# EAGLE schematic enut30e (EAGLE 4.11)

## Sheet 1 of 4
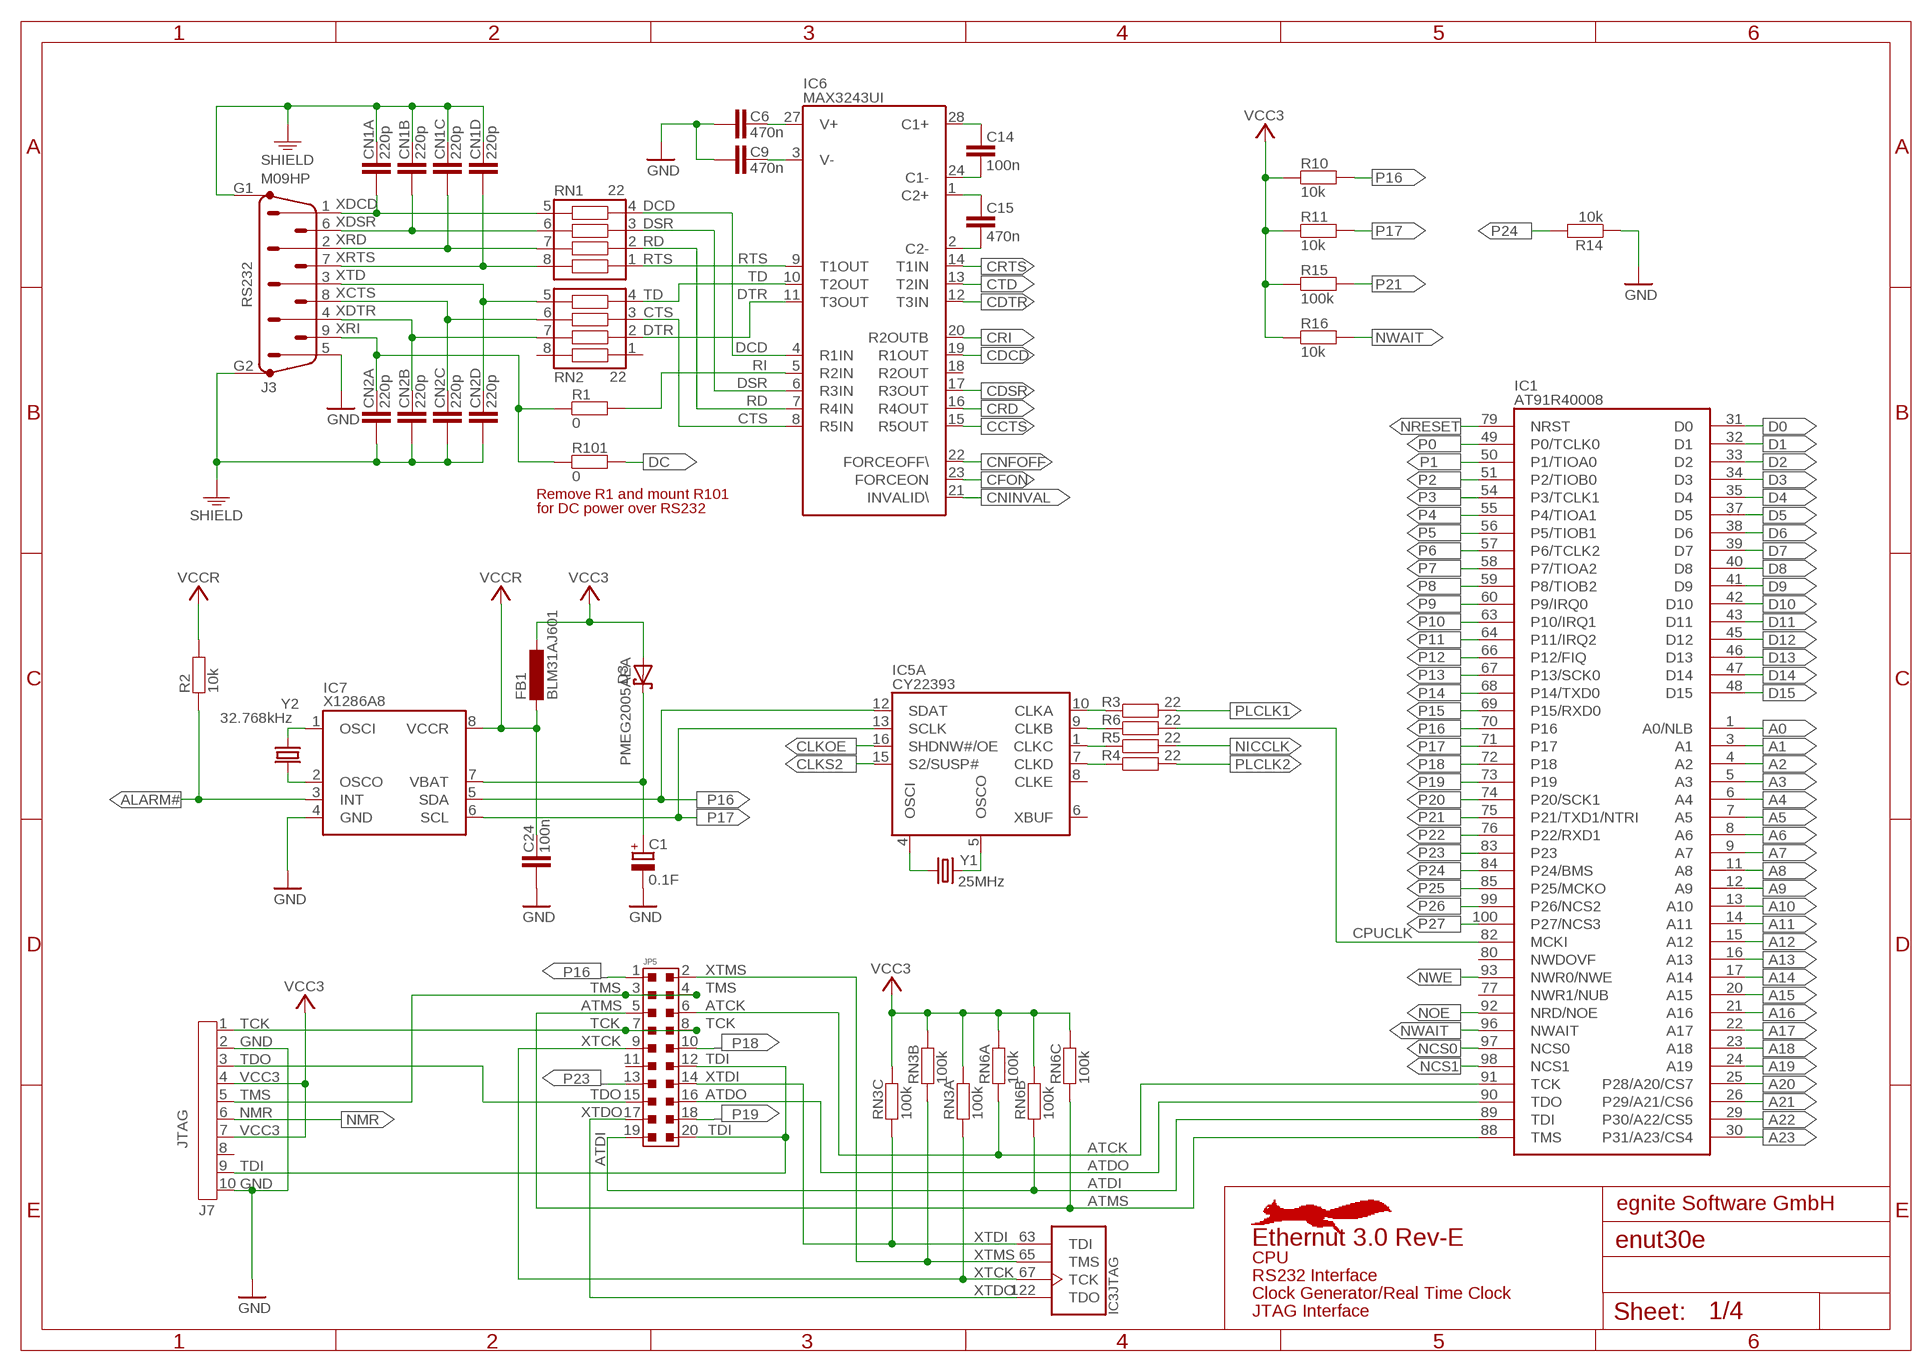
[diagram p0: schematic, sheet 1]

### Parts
C1  0.1F  FG0H104Z135  [CDL13_5]
C6  470n  C0603  [C0603]
C9  470n  C0603  [C0603]
C14  100n  C0603  [C0603]
C15  470n  C0603  [C0603]
C24  100n  C0603  [C0603]
CN1  220p  NCA1206  [NCA1206]
CN2  220p  NCA1206  [NCA1206]
D3  PMEG2005AEA  [SOD323]
FB1  BLM31AJ601  BLM31A  [BLM31]
IC1  AT91R40008  [TQFP100]
IC3  XC95144XLTQ144  [XC95_TQ144]
IC5  CY22393  [TSSOP16]
IC6  MAX3243UI  [TSSOP28]
IC7  X1286A8  [SOIC-8-209]
J3  M09HP  [M09HP]
J7  ML10A  [ML10A]
JP5  JP10X2  [JP10X2]
R1  0  R0603  [R0603]
R2  10k  R0603  [R0603]
R3  22  R0603  [R0603]
R4  22  R0603  [R0603]
R5  22  R0603  [R0603]
R6  22  R0603  [R0603]
R10  10k  R0603  [R0603]
R11  10k  R0603  [R0603]
R14  10k  R0603  [R0603]
R15  100k  R0603  [R0603]
R16  10k  R0603  [R0603]
R101  0  R1206  [R1206]
RN1  22  CAY16N  [CAY16]
RN2  22  CAY16N  [CAY16]
RN3  100k  CAY16  [CAY16]
RN6  100k  CAY16  [CAY16]
Y1  25MHz  CRYSTALHC49SM  [HC49SM]
Y2  32.768kHz  MC-146  [MC-146]

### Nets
A0: IC1.1(A0/NLB) ; also sheet 2
A1: IC1.3(A1) ; also sheet 2
A2: IC1.4(A2) ; also sheet 2,3
A3: IC1.5(A3) ; also sheet 2
A4: IC1.6(A4) ; also sheet 2
A5: IC1.7(A5) ; also sheet 2
A6: IC1.8(A6) ; also sheet 2
A7: IC1.9(A7) ; also sheet 2
A8 [AddrbusH]: IC1.11(A8) ; also sheet 2
A9 [AddrbusH]: IC1.12(A9) ; also sheet 2
A10 [AddrbusH]: IC1.13(A10) ; also sheet 2
A11 [AddrbusH]: IC1.14(A11) ; also sheet 2
A12 [AddrbusH]: IC1.15(A12) ; also sheet 2
A13 [AddrbusH]: IC1.16(A13) ; also sheet 2
A14 [AddrbusH]: IC1.17(A14) ; also sheet 2
A15 [AddrbusH]: IC1.20(A15) ; also sheet 2
A16: IC1.21(A16) ; also sheet 2
A17: IC1.22(A17) ; also sheet 2
A18: IC1.23(A18) ; also sheet 2
A19: IC1.24(A19) ; also sheet 2
A20: IC1.25(P28/A20/CS7) ; also sheet 2
A21: IC1.26(P29/A21/CS6) ; also sheet 2
A22: IC1.29(P30/A22/CS5) ; also sheet 2
A23: IC1.30(P31/A23/CS4) ; also sheet 2
ALARM#: IC7.3(INT) R2.1 ; also sheet 2
ATCK: IC1.91(TCK) JP5.6 RN6.1
ATDI: IC1.89(TDI) JP5.19 RN6.2
ATDO: IC1.90(TDO) JP5.16
ATMS: IC1.88(TMS) JP5.5 RN6.3
CCTS: IC6.15(R5OUT) ; also sheet 2
CDCD: IC6.19(R1OUT) ; also sheet 2
CDSR: IC6.17(R3OUT) ; also sheet 2
CDTR: IC6.12(T3IN) ; also sheet 2
CFON: IC6.23(FORCEON) ; also sheet 2
CLKA: IC5.10(A:CLKA) R3.1
CLKB: IC5.9(A:CLKB) R6.1
CLKC: IC5.1(A:CLKC) R5.1
CLKD: IC5.7(A:CLKD) R4.1
CLKOE: IC5.16(A:SHDNW#/OE) ; also sheet 2
CLKS2: IC5.15(A:S2/SUSP#) ; also sheet 2
CNFOFF: IC6.22(FORCEOFF\) ; also sheet 2
CNINVAL: IC6.21(INVALID\) ; also sheet 2
CPUCLK: IC1.82(MCKI) R6.2
CRD: IC6.16(R4OUT) ; also sheet 2
CRI: IC6.20(R2OUTB) ; also sheet 2
CRTS: IC6.14(T1IN) ; also sheet 2
CTD: IC6.13(T2IN) ; also sheet 2
CTS: IC6.8(R5IN) RN2.3
D0 [Databus]: IC1.31(D0) ; also sheet 2,3
D1 [Databus]: IC1.32(D1) ; also sheet 2,3
D2 [Databus]: IC1.33(D2) ; also sheet 2,3
D3 [Databus]: IC1.34(D3) ; also sheet 2,3
D4 [Databus]: IC1.35(D4) ; also sheet 2,3
D5 [Databus]: IC1.37(D5) ; also sheet 2,3
D6 [Databus]: IC1.38(D6) ; also sheet 2,3
D7 [Databus]: IC1.39(D7) ; also sheet 2,3
D8: IC1.40(D8) ; also sheet 2,3
D9: IC1.41(D9) ; also sheet 2,3
D10: IC1.42(D10) ; also sheet 2,3
D11: IC1.43(D11) ; also sheet 2,3
D12: IC1.45(D12) ; also sheet 2,3
D13: IC1.46(D13) ; also sheet 2,3
D14: IC1.47(D14) ; also sheet 2,3
D15: IC1.48(D15) ; also sheet 2,3
DC: R101.2 ; also sheet 2,4
DCD: IC6.4(R1IN) RN1.4
DSR: IC6.6(R3IN) RN1.3
DTR: IC6.11(T3OUT) RN2.2
GND: C1.- C6.2 C9.2 C24.2 IC7.4(GND) J3.5 J7.2 J7.10 R14.1 ; also sheet 2,3,4
N$1: C6.1 IC6.27(V+)
N$2: C9.1 IC6.3(V-)
N$3: C15.2 IC6.2(C2-)
N$8: C15.1 IC6.1(C2+)
N$9: C14.2 IC6.24(C1-)
N$10: C14.1 IC6.28(C1+)
N$45: IC5.4(A:OSCI) Y1.2
N$46: IC5.5(A:OSCO) Y1.1
NCS0: IC1.97(NCS0) ; also sheet 2
NCS1: IC1.98(NCS1) ; also sheet 3
NICCLK: R5.2 ; also sheet 3
NMR: J7.6 ; also sheet 2,4
NOE: IC1.92(NRD/NOE) ; also sheet 2,3
NRESET: IC1.79(NRST) ; also sheet 2,3,4
NWAIT: IC1.96(NWAIT) R16.2 ; also sheet 2,3
NWE: IC1.93(NWR0/NWE) ; also sheet 2,3
P0: IC1.49(P0/TCLK0) ; also sheet 2
P1: IC1.50(P1/TIOA0) ; also sheet 2
P2: IC1.51(P2/TIOB0) ; also sheet 2
P3: IC1.54(P3/TCLK1) ; also sheet 2
P4: IC1.55(P4/TIOA1) ; also sheet 2
P5: IC1.56(P5/TIOB1) ; also sheet 2
P6: IC1.57(P6/TCLK2) ; also sheet 2
P7: IC1.58(P7/TIOA2) ; also sheet 2
P8: IC1.59(P8/TIOB2) ; also sheet 2
P9: IC1.60(P9/IRQ0) ; also sheet 2
P10: IC1.63(P10/IRQ1) ; also sheet 3
P11: IC1.64(P11/IRQ2) ; also sheet 2
P12: IC1.66(P12/FIQ) ; also sheet 2
P13: IC1.67(P13/SCK0) ; also sheet 2
P14: IC1.68(P14/TXD0) ; also sheet 2
P15: IC1.69(P15/RXD0) ; also sheet 2
P16: IC1.70(P16) IC5.12(A:SDAT) IC7.5(SDA) JP5.1 R10.2 ; also sheet 2
P17: IC1.71(P17) IC5.13(A:SCLK) IC7.6(SCL) R11.2 ; also sheet 2
P18: IC1.72(P18) JP5.10 ; also sheet 2
P19: IC1.73(P19) JP5.18 ; also sheet 2
P20: IC1.74(P20/SCK1) ; also sheet 2
P21: IC1.75(P21/TXD1/NTRI) R15.2 ; also sheet 2
P22: IC1.76(P22/RXD1) ; also sheet 2
P23: IC1.83(P23) JP5.13 ; also sheet 2
P24: IC1.84(P24/BMS) R14.2 ; also sheet 2,3
P25: IC1.85(P25/MCKO) ; also sheet 2
P26: IC1.99(P26/NCS2) ; also sheet 2
P27: IC1.100(P27/NCS3) ; also sheet 2
PLCLK1: R3.2 ; also sheet 2
PLCLK2: R4.2 ; also sheet 2
RD: IC6.7(R4IN) RN1.2
RI: IC6.5(R2IN) R1.2
RTCX1: IC7.1(OSCI) Y2.1
RTCX2: IC7.2(OSCO) Y2.4
RTS: IC6.9(T1OUT) RN1.1
SHIELD: CN1.1 CN1.2 CN1.3 CN1.4 CN2.5 CN2.6 CN2.7 CN2.8 J3.G1 J3.G2 ; also sheet 2,3
TCK: J7.1 JP5.7 JP5.8
TD: IC6.10(T2OUT) RN2.4
TDI: J7.9 JP5.12 JP5.20
TDO: J7.3 JP5.15
TMS: J7.5 JP5.3 JP5.4
VBAT: C1.+ D3.C IC7.7(VBAT)
VCC3: D3.A FB1.1 J7.4 J7.7 R10.1 R11.1 R15.1 R16.1 RN3.6 RN3.7 RN3.8 RN6.6 RN6.7 RN6.8 ; also sheet 2,4
VCCR: C24.1 FB1.2 IC7.8(VCCR) R2.2
XCTS: CN2.3 J3.8 RN2.6
XDCD: CN1.8 J3.1 RN1.5
XDSR: CN1.7 J3.6 RN1.6
XDTR: CN2.2 J3.4 RN2.7
XRD: CN1.6 J3.2 RN1.7
XRI: CN2.1 J3.9 R1.1 R101.1
XRTS: CN1.5 J3.7 RN1.8
XTCK: IC3.67(TCK) JP5.9 RN3.1
XTD: CN2.4 J3.3 RN2.5
XTDI: IC3.63(TDI) JP5.14 RN3.3
XTDO: IC3.122(TDO) JP5.17
XTMS: IC3.65(TMS) JP5.2 RN3.2
Unconnected: J7.8 JP5.11 RN2.1 RN2.8 RN3.4 RN3.5 RN6.4 RN6.5

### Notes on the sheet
- RS232
- Remove R1 and mount R101
- for DC power over RS232
- JTAG
- egnite Software GmbH
- Ethernut 3.0 Rev-E
- CPU
- RS232 Interface
- Clock Generator/Real Time Clock
- JTAG Interface

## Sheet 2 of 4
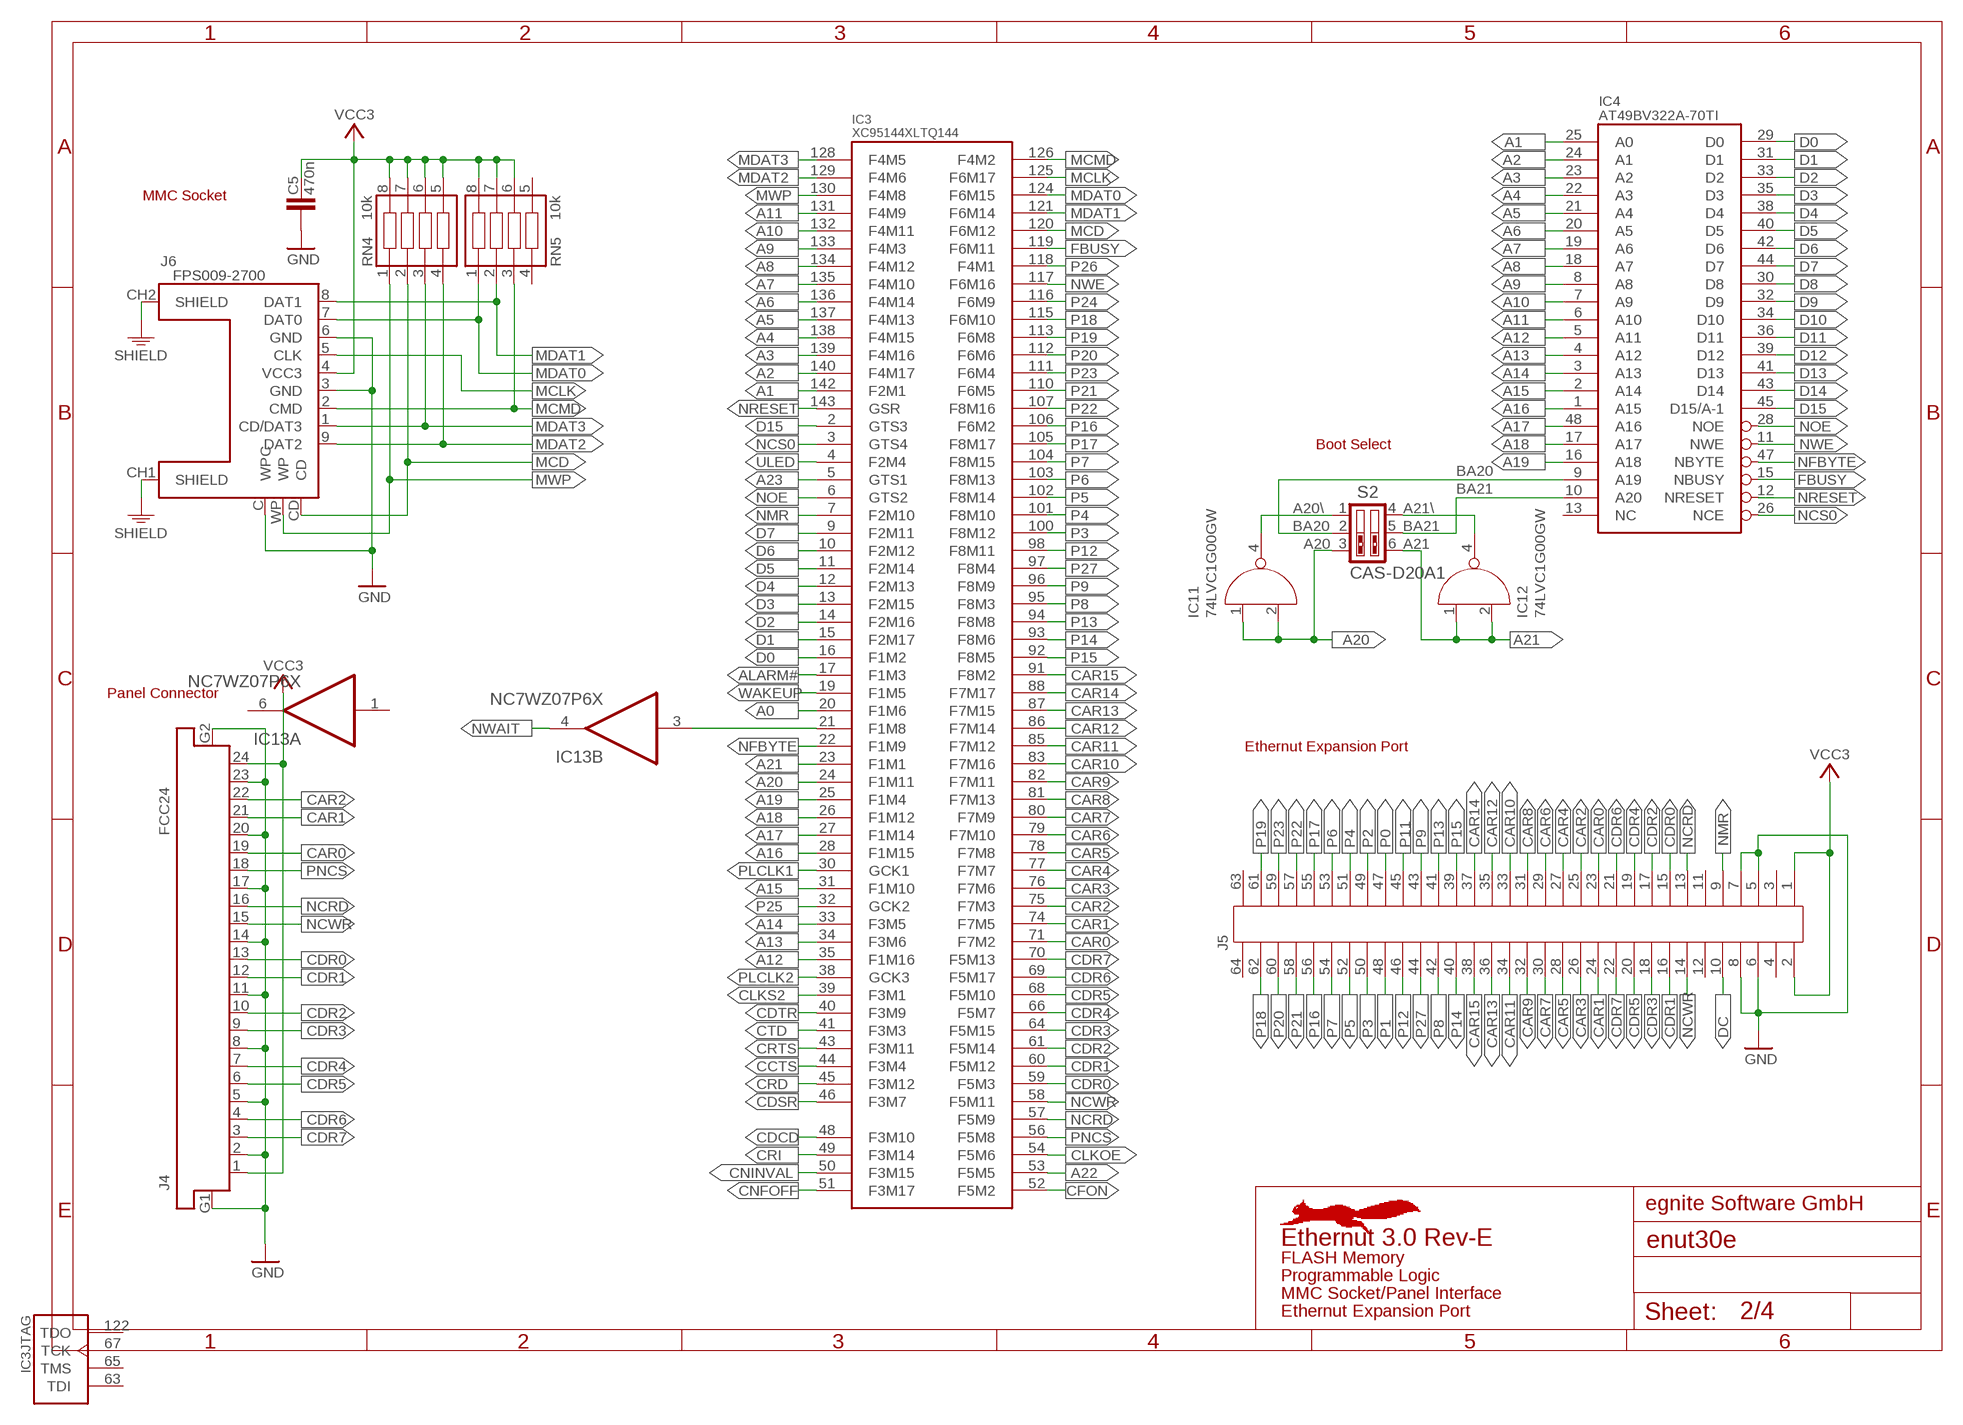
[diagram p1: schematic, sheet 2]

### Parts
C5  470n  C0603  [C0603]
IC4  AT49BV322A-70TI  [TSOP48]
IC11  74LVC1G00GW  [SOT353]
IC12  74LVC1G00GW  [SOT353]
IC13  NC7WZ07P6X  [SOT363]
J4  FCC24  [FFC-52437]
J5  NUTEXP  [NUTEXP]
J6  FPS009-2700  [FPS009-2700]
RN4  10k  CAY16N  [CAY16]
RN5  10k  CAY16N  [CAY16]
S2  CAS-D20A1  [CAS-D20A1]

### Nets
A0: IC3.20(F1M6) ; also sheet 1
A1: IC3.142(F2M1) IC4.25(A0) ; also sheet 1
A2: IC3.140(F4M17) IC4.24(A1) ; also sheet 1,3
A3: IC3.139(F4M16) IC4.23(A2) ; also sheet 1
A4: IC3.138(F4M15) IC4.22(A3) ; also sheet 1
A5: IC3.137(F4M13) IC4.21(A4) ; also sheet 1
A6: IC3.136(F4M14) IC4.20(A5) ; also sheet 1
A7: IC3.135(F4M10) IC4.19(A6) ; also sheet 1
A8 [AddrbusH]: IC3.134(F4M12) IC4.18(A7) ; also sheet 1
A9 [AddrbusH]: IC3.133(F4M3) IC4.8(A8) ; also sheet 1
A10 [AddrbusH]: IC3.132(F4M11) IC4.7(A9) ; also sheet 1
A11 [AddrbusH]: IC3.131(F4M9) IC4.6(A10) ; also sheet 1
A12 [AddrbusH]: IC3.35(F1M16) IC4.5(A11) ; also sheet 1
A13 [AddrbusH]: IC3.34(F3M6) IC4.4(A12) ; also sheet 1
A14 [AddrbusH]: IC3.33(F3M5) IC4.3(A13) ; also sheet 1
A15 [AddrbusH]: IC3.31(F1M10) IC4.2(A14) ; also sheet 1
A16: IC3.28(F1M15) IC4.1(A15) ; also sheet 1
A17: IC3.27(F1M14) IC4.48(A16) ; also sheet 1
A18: IC3.26(F1M12) IC4.17(A17) ; also sheet 1
A19: IC3.25(F1M4) IC4.16(A18) ; also sheet 1
A20: IC3.24(F1M11) IC11.1(I0) IC11.2(I1) S2.3(3A) ; also sheet 1
A20\: IC11.4(O) S2.1(1A)
A21: IC3.23(F1M1) IC12.1(I0) IC12.2(I1) S2.6(3B) ; also sheet 1
A21\: IC12.4(O) S2.4(1B)
A22: IC3.53(F5M5) ; also sheet 1
A23: IC3.5(GTS1) ; also sheet 1
ALARM#: IC3.17(F1M3) ; also sheet 1
BA20: IC4.9(A19) S2.2(2A)
BA21: IC4.10(A20) S2.5(2B)
CAR0: IC3.71(F7M2) J4.19 J5.23
CAR1: IC3.74(F7M5) J4.21 J5.24
CAR2: IC3.75(F7M3) J4.22 J5.25
CAR3: IC3.76(F7M6) J5.26
CAR4: IC3.77(F7M7) J5.27
CAR5: IC3.78(F7M8) J5.28
CAR6: IC3.79(F7M10) J5.29
CAR7: IC3.80(F7M9) J5.30
CAR8: IC3.81(F7M13) J5.31
CAR9: IC3.82(F7M11) J5.32
CAR10: IC3.83(F7M16) J5.33
CAR11: IC3.85(F7M12) J5.34
CAR12: IC3.86(F7M14) J5.35
CAR13: IC3.87(F7M15) J5.36
CAR14: IC3.88(F7M17) J5.37
CAR15: IC3.91(F8M2) J5.38
CCTS: IC3.44(F3M4) ; also sheet 1
CDCD: IC3.48(F3M10) ; also sheet 1
CDR0: IC3.59(F5M3) J4.13 J5.15
CDR1: IC3.60(F5M12) J4.12 J5.16
CDR2: IC3.61(F5M14) J4.10 J5.17
CDR3: IC3.64(F5M15) J4.9 J5.18
CDR4: IC3.66(F5M7) J4.7 J5.19
CDR5: IC3.68(F5M10) J4.6 J5.20
CDR6: IC3.69(F5M17) J4.4 J5.21
CDR7: IC3.70(F5M13) J4.3 J5.22
CDSR: IC3.46(F3M7) ; also sheet 1
CDTR: IC3.40(F3M9) ; also sheet 1
CFON: IC3.52(F5M2) ; also sheet 1
CLKOE: IC3.54(F5M6) ; also sheet 1
CLKS2: IC3.39(F3M1) ; also sheet 1
CNFOFF: IC3.51(F3M17) ; also sheet 1
CNINVAL: IC3.50(F3M15) ; also sheet 1
CRD: IC3.45(F3M12) ; also sheet 1
CRI: IC3.49(F3M14) ; also sheet 1
CRTS: IC3.43(F3M11) ; also sheet 1
CTD: IC3.41(F3M3) ; also sheet 1
D0 [Databus]: IC3.16(F1M2) IC4.29(D0) ; also sheet 1,3
D1 [Databus]: IC3.15(F2M17) IC4.31(D1) ; also sheet 1,3
D2 [Databus]: IC3.14(F2M16) IC4.33(D2) ; also sheet 1,3
D3 [Databus]: IC3.13(F2M15) IC4.35(D3) ; also sheet 1,3
D4 [Databus]: IC3.12(F2M13) IC4.38(D4) ; also sheet 1,3
D5 [Databus]: IC3.11(F2M14) IC4.40(D5) ; also sheet 1,3
D6 [Databus]: IC3.10(F2M12) IC4.42(D6) ; also sheet 1,3
D7 [Databus]: IC3.9(F2M11) IC4.44(D7) ; also sheet 1,3
D8: IC4.30(D8) ; also sheet 1,3
D9: IC4.32(D9) ; also sheet 1,3
D10: IC4.34(D10) ; also sheet 1,3
D11: IC4.36(D11) ; also sheet 1,3
D12: IC4.39(D12) ; also sheet 1,3
D13: IC4.41(D13) ; also sheet 1,3
D14: IC4.43(D14) ; also sheet 1,3
D15: IC3.2(GTS3) IC4.45(D15/A-1) ; also sheet 1,3
DC: J5.10 ; also sheet 1,4
FBUSY: IC3.119(F6M11) IC4.15(NBUSY)
GND: C5.2 J4.2 J4.5 J4.8 J4.11 J4.14 J4.17 J4.20 J4.23 J4.G1 J4.G2 J5.5 J5.6 J5.7 J5.8 J6.3(GND) J6.6(GND) J6.C(WPC) ; also sheet 1,3,4
MCD: IC3.120(F6M12) J6.CD RN4.2
MCLK: IC3.125(F6M17) J6.5(CLK)
MCMD: IC3.126(F4M2) J6.2(CMD) RN5.3
MDAT0: IC3.124(F6M15) J6.7(DAT0) RN5.1
MDAT1: IC3.121(F6M14) J6.8(DAT1) RN5.2
MDAT2: IC3.129(F4M6) J6.9(DAT2) RN4.4
MDAT3: IC3.128(F4M5) J6.1(CD/DAT3) RN4.3
MWP: IC3.130(F4M8) J6.WP RN4.1
NCRD: IC3.57(F5M9) J4.16 J5.13
NCS0: IC3.3(GTS4) IC4.26(NCE) ; also sheet 1
NCWAIT: IC3.21(F1M8) IC13.3(B:I)
NCWR: IC3.58(F5M11) J4.15 J5.14
NFBYTE: IC3.22(F1M9) IC4.47(NBYTE)
NMR: IC3.7(F2M10) J5.9 ; also sheet 1,4
NOE: IC3.6(GTS2) IC4.28(NOE) ; also sheet 1,3
NRESET: IC3.143(GSR) IC4.12(NRESET) ; also sheet 1,3,4
NWAIT: IC13.4(B:O) ; also sheet 1,3
NWE: IC3.117(F6M16) IC4.11(NWE) ; also sheet 1,3
P0: J5.47 ; also sheet 1
P1: J5.48 ; also sheet 1
P2: J5.49 ; also sheet 1
P3: IC3.100(F8M12) J5.50 ; also sheet 1
P4: IC3.101(F8M10) J5.51 ; also sheet 1
P5: IC3.102(F8M14) J5.52 ; also sheet 1
P6: IC3.103(F8M13) J5.53 ; also sheet 1
P7: IC3.104(F8M15) J5.54 ; also sheet 1
P8: IC3.95(F8M3) J5.42 ; also sheet 1
P9: IC3.96(F8M9) J5.43 ; also sheet 1
P11: J5.45 ; also sheet 1
P12: IC3.98(F8M11) J5.46 ; also sheet 1
P13: IC3.94(F8M8) J5.41 ; also sheet 1
P14: IC3.93(F8M6) J5.40 ; also sheet 1
P15: IC3.92(F8M5) J5.39 ; also sheet 1
P16: IC3.106(F6M2) J5.56 ; also sheet 1
P17: IC3.105(F8M17) J5.55 ; also sheet 1
P18: IC3.115(F6M10) J5.62 ; also sheet 1
P19: IC3.113(F6M8) J5.61 ; also sheet 1
P20: IC3.112(F6M6) J5.60 ; also sheet 1
P21: IC3.110(F6M5) J5.58 ; also sheet 1
P22: IC3.107(F8M16) J5.57 ; also sheet 1
P23: IC3.111(F6M4) J5.59 ; also sheet 1
P24: IC3.116(F6M9) ; also sheet 1,3
P25: IC3.32(GCK2) ; also sheet 1
P26: IC3.118(F4M1) ; also sheet 1
P27: IC3.97(F8M4) J5.44 ; also sheet 1
PLCLK1: IC3.30(GCK1) ; also sheet 1
PLCLK2: IC3.38(GCK3) ; also sheet 1
PNCS: IC3.56(F5M8) J4.18
SHIELD: J6.CH1(SHIELD) J6.CH2(SHIELD) ; also sheet 1,3
ULED: IC3.4(F2M4) ; also sheet 4
VCC3: C5.1 J4.1 J4.24 J5.1 J5.2 J6.4(VCC3) RN4.5 RN4.6 RN4.7 RN4.8 RN5.6 RN5.7 RN5.8 ; also sheet 1,4
WAKEUP: IC3.19(F1M5) ; also sheet 3
Unconnected: IC4.13(NC) J5.3 J5.4 J5.11 J5.12 J5.63 J5.64 RN5.4 RN5.5

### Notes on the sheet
- MMC Socket
- Boot Select
- Panel Connector
- Ethernut Expansion Port
- egnite Software GmbH
- Ethernut 3.0 Rev-E
- FLASH Memory
- Programmable Logic
- MMC Socket/Panel Interface
- Ethernut Expansion Port

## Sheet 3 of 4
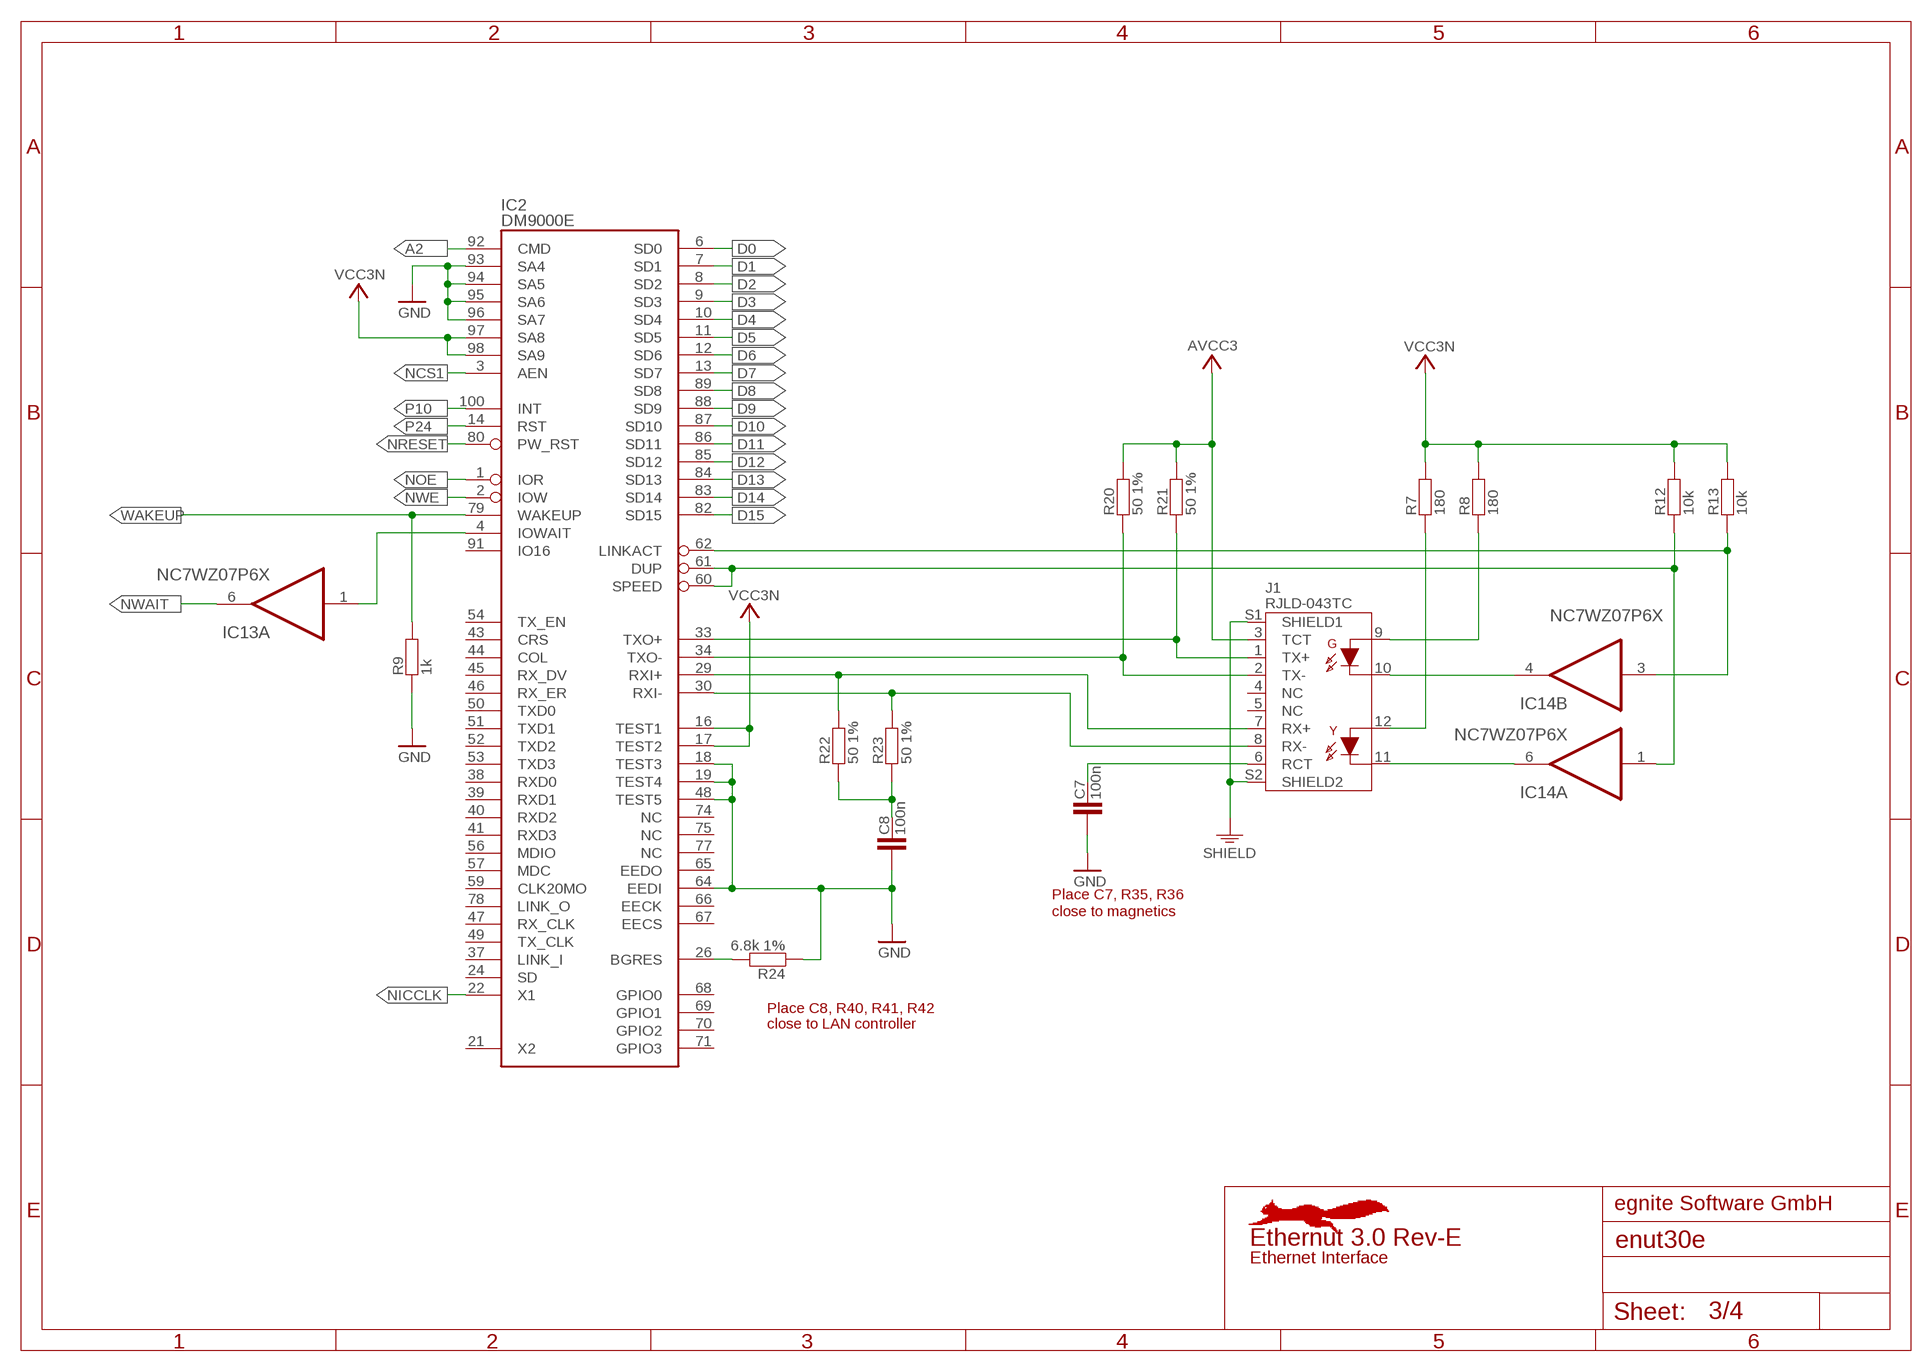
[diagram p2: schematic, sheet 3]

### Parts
C7  100n  C0603  [C0603]
C8  100n  C0603  [C0603]
IC2  DM9000E  [LQFP100]
IC14  NC7WZ07P6X  [SOT363]
J1  RJLD-043TC  [RJLD-043TC]
R7  180  R0603  [R0603]
R8  180  R0603  [R0603]
R9  1k  R0603  [R0603]
R12  10k  R0603  [R0603]
R13  10k  R0603  [R0603]
R20  50 1%  R0603  [R0603]
R21  50 1%  R0603  [R0603]
R22  50 1%  R0603  [R0603]
R23  50 1%  R0603  [R0603]
R24  6.8k 1%  R0603  [R0603]

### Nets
A2: IC2.92(CMD) ; also sheet 1,2
ALEDA: J1.12(YA) R7.1
ALEDC: IC14.6(A:O) J1.11(YC)
AVCC3: J1.3(TCT) R20.2 R21.2 ; also sheet 4
BIAS: IC2.26(BGRES) R24.2
D0 [Databus]: IC2.6(SD0) ; also sheet 1,2
D1 [Databus]: IC2.7(SD1) ; also sheet 1,2
D2 [Databus]: IC2.8(SD2) ; also sheet 1,2
D3 [Databus]: IC2.9(SD3) ; also sheet 1,2
D4 [Databus]: IC2.10(SD4) ; also sheet 1,2
D5 [Databus]: IC2.11(SD5) ; also sheet 1,2
D6 [Databus]: IC2.12(SD6) ; also sheet 1,2
D7 [Databus]: IC2.13(SD7) ; also sheet 1,2
D8: IC2.89(SD8) ; also sheet 1,2
D9: IC2.88(SD9) ; also sheet 1,2
D10: IC2.87(SD10) ; also sheet 1,2
D11: IC2.86(SD11) ; also sheet 1,2
D12: IC2.85(SD12) ; also sheet 1,2
D13: IC2.84(SD13) ; also sheet 1,2
D14: IC2.83(SD14) ; also sheet 1,2
D15: IC2.82(SD15) ; also sheet 1,2
ETHWAIT: IC2.4(IOWAIT) IC13.1(A:I)
GND: C7.2 C8.2 IC2.18(TEST3) IC2.19(TEST4) IC2.48(TEST5) IC2.64(EEDI) IC2.93(SA4) IC2.94(SA5) IC2.95(SA6) IC2.96(SA7) R9.1 R24.1 ; also sheet 1,2,4
LLEDA: J1.9(GA) R8.1
LLEDC: IC14.4(B:O) J1.10(GC)
NCS1: IC2.3(AEN) ; also sheet 1
NICCLK: IC2.22(X1) ; also sheet 1
NLEDA\: IC2.62(LINKACT) IC14.3(B:I) R13.1
NLEDB\: IC2.60(SPEED) IC2.61(DUP) IC14.1(A:I) R12.1
NOE: IC2.1(IOR) ; also sheet 1,2
NRESET: IC2.80(PW_RST) ; also sheet 1,2,4
NWAIT: IC13.6(A:O) ; also sheet 1,2
NWE: IC2.2(IOW) ; also sheet 1,2
P10: IC2.100(INT) ; also sheet 1
P24: IC2.14(RST) ; also sheet 1,2
RCT: C7.1 J1.6(RCT)
RXIC: C8.1 R22.1 R23.1
SHIELD: J1.S1(SHIELD1) J1.S2(SHIELD2) ; also sheet 1,2
TPI+: IC2.29(RXI+) J1.7(RX+) R22.2
TPI-: IC2.30(RXI-) J1.8(RX-) R23.2
TPO+: IC2.33(TXO+) J1.1(TX+) R21.1
TPO-: IC2.34(TXO-) J1.2(TX-) R20.1
VCC3N: IC2.16(TEST1) IC2.17(TEST2) IC2.97(SA8) IC2.98(SA9) R7.2 R8.2 R12.2 R13.2 ; also sheet 4
WAKEUP: IC2.79(WAKEUP) R9.2 ; also sheet 2
Unconnected: J1.4(NC) J1.5(NC)

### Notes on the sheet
- Place C7, R35, R36
- close to magnetics
- Place C8, R40, R41, R42
- close to LAN controller
- egnite Software GmbH
- Ethernut 3.0 Rev-E
- Ethernet Interface

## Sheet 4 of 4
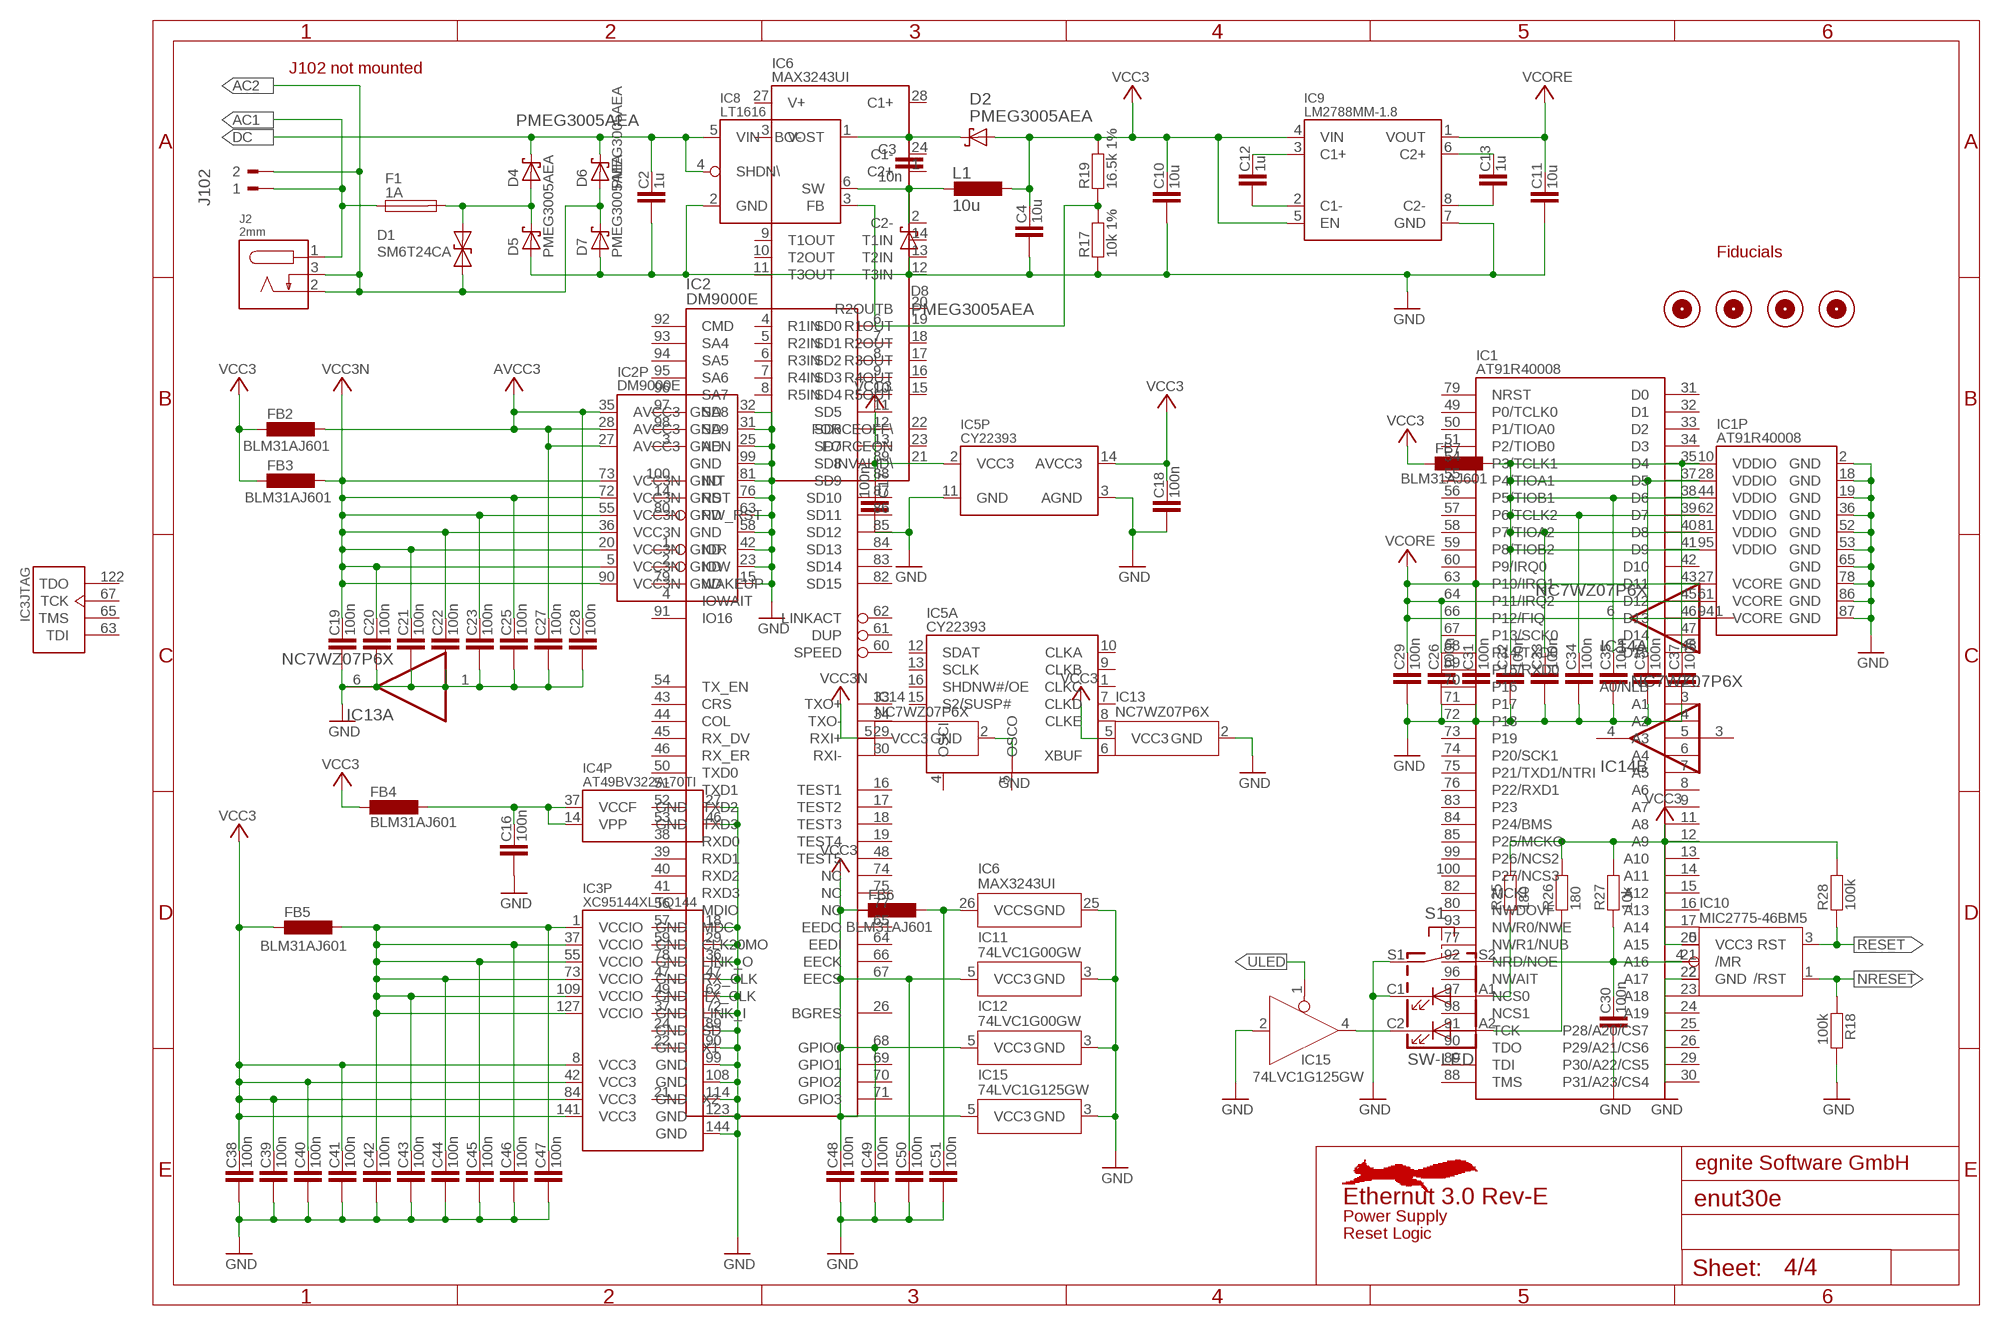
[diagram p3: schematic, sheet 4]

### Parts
C2  1u  C0805  [C0805]
C3  10n  C0603  [C0603]
C4  10u  C0805  [C0805]
C10  10u  C0805  [C0805]
C11  10u  C0805  [C0805]
C12  1u  C0805  [C0805]
C13  1u  C0805  [C0805]
C16  100n  C0603  [C0603]
C17  100n  C0603  [C0603]
C18  100n  C0603  [C0603]
C19  100n  C0603  [C0603]
C20  100n  C0603  [C0603]
C21  100n  C0603  [C0603]
C22  100n  C0603  [C0603]
C23  100n  C0603  [C0603]
C25  100n  C0603  [C0603]
C26  100n  C0603  [C0603]
C27  100n  C0603  [C0603]
C28  100n  C0603  [C0603]
C29  100n  C0603  [C0603]
C30  100n  C0603  [C0603]
C31  100n  C0603  [C0603]
C32  100n  C0603  [C0603]
C33  100n  C0603  [C0603]
C34  100n  C0603  [C0603]
C35  100n  C0603  [C0603]
C36  100n  C0603  [C0603]
C37  100n  C0603  [C0603]
C38  100n  C0603  [C0603]
C39  100n  C0603  [C0603]
C40  100n  C0603  [C0603]
C41  100n  C0603  [C0603]
C42  100n  C0603  [C0603]
C43  100n  C0603  [C0603]
C44  100n  C0603  [C0603]
C45  100n  C0603  [C0603]
C46  100n  C0603  [C0603]
C47  100n  C0603  [C0603]
C48  100n  C0603  [C0603]
C49  100n  C0603  [C0603]
C50  100n  C0603  [C0603]
C51  100n  C0603  [C0603]
D1  SM6T24CA  SM6T  [SMB]
D2  PMEG3005AEA  [SOD323]
D4  PMEG3005AEA  [SOD323]
D5  PMEG3005AEA  [SOD323]
D6  PMEG3005AEA  [SOD323]
D7  PMEG3005AEA  [SOD323]
D8  PMEG3005AEA  [SOD323]
F1  1A  OMNI-BLOK  [OMNI-BLOK]
FB2  BLM31AJ601  BLM31A  [BLM31]
FB3  BLM31AJ601  BLM31A  [BLM31]
FB4  BLM31AJ601  BLM31A  [BLM31]
FB5  BLM31AJ601  BLM31A  [BLM31]
FB6  BLM31AJ601  BLM31A  [BLM31]
FB7  BLM31AJ601  BLM31A  [BLM31]
FM1  FIDUCIAL-2MM  [FIDUCIAL-2MM]
FM2  FIDUCIAL-2MM  [FIDUCIAL-2MM]
FM3  FIDUCIAL-2MM  [FIDUCIAL-2MM]
FM4  FIDUCIAL-2MM  [FIDUCIAL-2MM]
IC8  LT1616  [TSOT-23-6]
IC9  LM2788MM-1.8  [MSOP-8]
IC10  MIC2775-46BM5  [SOT23-5L]
IC15  74LVC1G125GW  [SOT353]
J2  2mm  TDC-002-3  [TDC-002-3]
J102  180-2  [180-2]
L1  10u  MSS5131  [MSS5131]
R17  10k 1%  R0603  [R0603]
R18  100k  R0603  [R0603]
R19  16.5k 1%  R0603  [R0603]
R25  180  R0603  [R0603]
R26  180  R0603  [R0603]
R27  10k  R0603  [R0603]
R28  100k  R0603  [R0603]
S1  SW-LED  [PTS-026]

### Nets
AC1 [Supply1A]: F1.1 J2.1 J102.1
AC2 [Supply1A]: D1.A D6.A D7.C J2.2 J2.3 J102.2
ACF: D1.C D4.A D5.C F1.2
AVCC3: C27.1 C28.1 FB2.1 IC2.27(AVCC3) IC2.28(AVCC3) IC2.35(AVCC3) ; also sheet 3
DC: C2.1 D4.C D6.C IC8.4(SHDN\) IC8.5(VIN) ; also sheet 1,2
GND: C2.2 C4.2 C10.2 C11.2 C16.2 C17.2 C18.2 C19.2 C20.2 C21.2 C22.2 C23.2 C25.2 C26.2 C27.2 C28.2 C29.2 C30.2 C31.2 C32.2 C33.2 C34.2 C35.2 C36.2 C37.2 C38.2 C39.2 C40.2 C41.2 C42.2 C43.2 C44.2 C45.2 C46.2 C47.2 C48.2 C49.2 C50.2 C51.2 D5.A D7.A D8.A IC1.2(GND) IC1.18(GND) IC1.19(GND) IC1.36(GND) IC1.52(GND) IC1.53(GND) IC1.65(GND) IC1.78(GND) IC1.86(GND) IC1.87(GND) IC2.15(GND) IC2.23(GND) IC2.25(GND) IC2.31(GND) IC2.32(GND) IC2.42(GND) IC2.58(GND) IC2.63(GND) IC2.76(GND) IC2.81(GND) IC2.99(GND) IC3.18(GND) IC3.29(GND) IC3.36(GND) IC3.47(GND) IC3.62(GND) IC3.72(GND) IC3.89(GND) IC3.90(GND) IC3.99(GND) IC3.108(GND) IC3.114(GND) IC3.123(GND) IC3.144(GND) IC4.27(GND) IC4.46(GND) IC5.3(P:AGND) IC5.11(P:GND) IC6.25(GND) IC8.2(GND) IC9.7(GND) IC10.2(GND) IC11.3(GND) IC12.3(GND) IC13.2(P:GND) IC14.2(P:GND) IC15.2(I) IC15.3(GND) R17.1 R18.2 S1.C1 S1.S1 ; also sheet 1,2,3
N$5: IC15.4(O) S1.C2
N$13: IC8.3(FB) R17.2 R19.1
N$18: C12.1 IC9.3(C1+)
N$19: C12.2 IC9.2(C1-)
N$21: C13.1 IC9.6(C2+)
N$23: C13.2 IC9.8(C2-)
N$49: R25.1 S1.A1
N$50: R26.1 S1.A2
NMR: C30.1 IC10.4(/MR) R27.1 S1.S2 ; also sheet 1,2
NRESET: IC10.1(/RST) R18.1 ; also sheet 1,2,3
RESET: IC10.3(RST) R28.1
ULED: IC15.1(OE) ; also sheet 2
VBOOST: C3.1 D2.C IC8.1(BOOST)
VCC3: C4.1 C10.1 C17.1 C18.1 C38.1 C39.1 C40.1 C41.1 C48.1 C49.1 C50.1 D2.A FB2.2 FB3.2 FB4.2 FB5.2 FB6.2 FB7.2 IC3.8(VCC3) IC3.42(VCC3) IC3.84(VCC3) IC3.141(VCC3) IC5.2(P:VCC3) IC5.14(P:AVCC3) IC9.4(VIN) IC9.5(EN) IC10.5(VCC3) IC11.5(VCC3) IC12.5(VCC3) IC13.5(P:VCC3) IC15.5(VCC3) L1.1 R19.2 R25.2 R26.2 R27.2 R28.2 ; also sheet 1,2
VCC3N: C19.1 C20.1 C21.1 C22.1 C23.1 C25.1 FB3.1 IC2.5(VCC3N) IC2.20(VCC3N) IC2.36(VCC3N) IC2.55(VCC3N) IC2.72(VCC3N) IC2.73(VCC3N) IC2.90(VCC3N) IC14.5(P:VCC3) ; also sheet 3
VCCF: C16.1 FB4.1 IC4.14(VPP) IC4.37(VCCF)
VCCIO: C42.1 C43.1 C44.1 C45.1 C46.1 C47.1 FB5.1 IC3.1(VCCIO) IC3.37(VCCIO) IC3.55(VCCIO) IC3.73(VCCIO) IC3.109(VCCIO) IC3.127(VCCIO)
VCCS: C51.1 FB6.1 IC6.26(VCCS)
VCORE: C11.1 C26.1 C29.1 C31.1 IC1.27(VCORE) IC1.61(VCORE) IC1.94(VCORE) IC9.1(VOUT)
VDDIO: C32.1 C33.1 C34.1 C35.1 C36.1 C37.1 FB7.1 IC1.10(VDDIO) IC1.28(VDDIO) IC1.44(VDDIO) IC1.62(VDDIO) IC1.81(VDDIO) IC1.95(VDDIO)
VSWITCH: C3.2 D8.C IC8.6(SW) L1.2
Unconnected: IC1.77(NWR1/NUB) IC1.80(NWDOVF) IC2.21(X2) IC2.24(SD) IC2.37(LINK_I) IC2.38(RXD0) IC2.39(RXD1) IC2.40(RXD2) IC2.41(RXD3) IC2.43(CRS) IC2.44(COL) IC2.45(RX_DV) IC2.46(RX_ER) IC2.47(RX_CLK) IC2.49(TX_CLK) IC2.50(TXD0) IC2.51(TXD1) IC2.52(TXD2) IC2.53(TXD3) IC2.54(TX_EN) IC2.56(MDIO) IC2.57(MDC) IC2.59(CLK20MO) IC2.65(EEDO) IC2.66(EECK) IC2.67(EECS) IC2.68(GPIO0) IC2.69(GPIO1) IC2.70(GPIO2) IC2.71(GPIO3) IC2.74(NC) IC2.75(NC) IC2.77(NC) IC2.78(LINK_O) IC2.91(IO16) IC5.6(A:XBUF) IC5.8(A:CLKE) IC6.18(R2OUT)

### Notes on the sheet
- J102 not mounted
- Fiducials
- egnite Software GmbH
- Ethernut 3.0 Rev-E
- Power Supply
- Reset Logic

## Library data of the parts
C1 = enut3:FG0H104Z: Double Layer Capacitor
C2-C51 = enut3:C: Ceramic Chip Capacitor
CN1 CN2 = enut3:NCA1206: Ceramic Chip Capacitor Array NIC Components
D1 = enut202:SM6T: Bidirectional Transient Voltage Suppressor
D2-D8 = enut3:PMEG*05AEA: Schottky Barrier Rectifier
F1 = enut3:OMNI-BLOK: Littlefuse OMNI-BLOK Fuseholder with Fuse
FB1-FB7 = enut3:BLM31A: Murata Ferrite Bead
FM1-FM4 = enut3:FIDUCIAL
IC1 = enut3:AT91R40008: Atmel ARM7 CPU
IC2 = enut3:DM9000E: Davicom Ethernet Controller ISA to Ethernet MAC controller with integrated 10/100 PHY
IC3 = enut3:XC95144XLTQ144: Xilinx CPLD
IC4 = enut3:AT49BV322A*: Atmel 32 Mbit 3V Flash Memory 2 MByte x 16 or 4 MByte x 8
IC5 = enut3:CY22393: Cypress Programmable Clock Generator
IC6 = enut3:MAX3243*: RS-232 Transceivers with AutoShutdown 1µA Supply-Current, True +3V to +5.5V http://dbserv.maxim-ic.com/
IC7 = enut3:X1286
IC8 = enut3:LT1616: Linear Technology Step Down Switching Regulator
IC9 = enut3:LM2788: National Semi Step-Down Switched Capacitor Voltage Converter 120mA High Efficiency Step-Down Switched Capacitor Voltage Converter
IC10 = enut3:MIC2775-*: Micrel Voltage Supervisor
IC11 IC12 = enut3:74*1G00: Philips Picogate
IC13 IC14 = enut3:NC7*07: TinyLogic Inverter - Open Drain Output WV High Speed: 0.9V-3.6V Supply, 3.6V tolerant, 1ns, 24mA Drive WZ Large V Range: 1.65V-5.5V Supply, 5V tolerant, 1.9ns, 24mA Drive
IC15 = enut3:74*1G125: Philips Picogate Bus buffer/line drivers; 3-state
J1 = enut3:RJLD-043TC
J2 = enut3:TDC-002-3: DC Power Socket
J3 = enut3:M09HP: SUB-D
J4 = enut3:FCC24: Flat Cable Connector
J5 = enut3:NUTEXP: Pin Header 2 x 32 with 2.54 mm grid
J6 = enut3:FPS009-2700: Yamaichi SD Card & MMC Socket
J7 = enut3:ML10: Pinheader 2 x 5 with 2.54 mm grid, boxed (JTAG)
J102 = enut3:180-2: WEIDMUELLER CLAMP CONNECTOR
JP5 = enut3:JP10X2: Pinheader 2 x 10 with 2mm grid
L1 = enut3:MSS5131: Coilcraft Power Inductor
R1-R28 R101 = enut3:R: Chip Resistor
RN1 RN2 RN4 RN5 = enut3:CAY16N: Resistor Array Single schematic symbol
RN3 RN6 = enut3:CAY16: Chip Resistor Array Multiple schematic symbols
S1 = enut3:SW-LED: Citizen Lumiswitch with 2 LEDs LS9 (20 mA LEDs)
S2 = enut3:CAS-D20A1: SMD Slide Switch
Y1 = enut3:CRYSTAL: Crystal
Y2 = enut3:MC-146: Clock Crystal SMD

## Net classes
1 Supply1A: width 0.61 mm
4 Ground: width 0.406 mm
